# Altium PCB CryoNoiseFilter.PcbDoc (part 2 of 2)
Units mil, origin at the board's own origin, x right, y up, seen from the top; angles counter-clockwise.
Board outline 2990 x 2110 mil, 2 copper layers (Top Layer, Bottom Layer); 246 components, 223 nets, 580 pads, 66 vias.
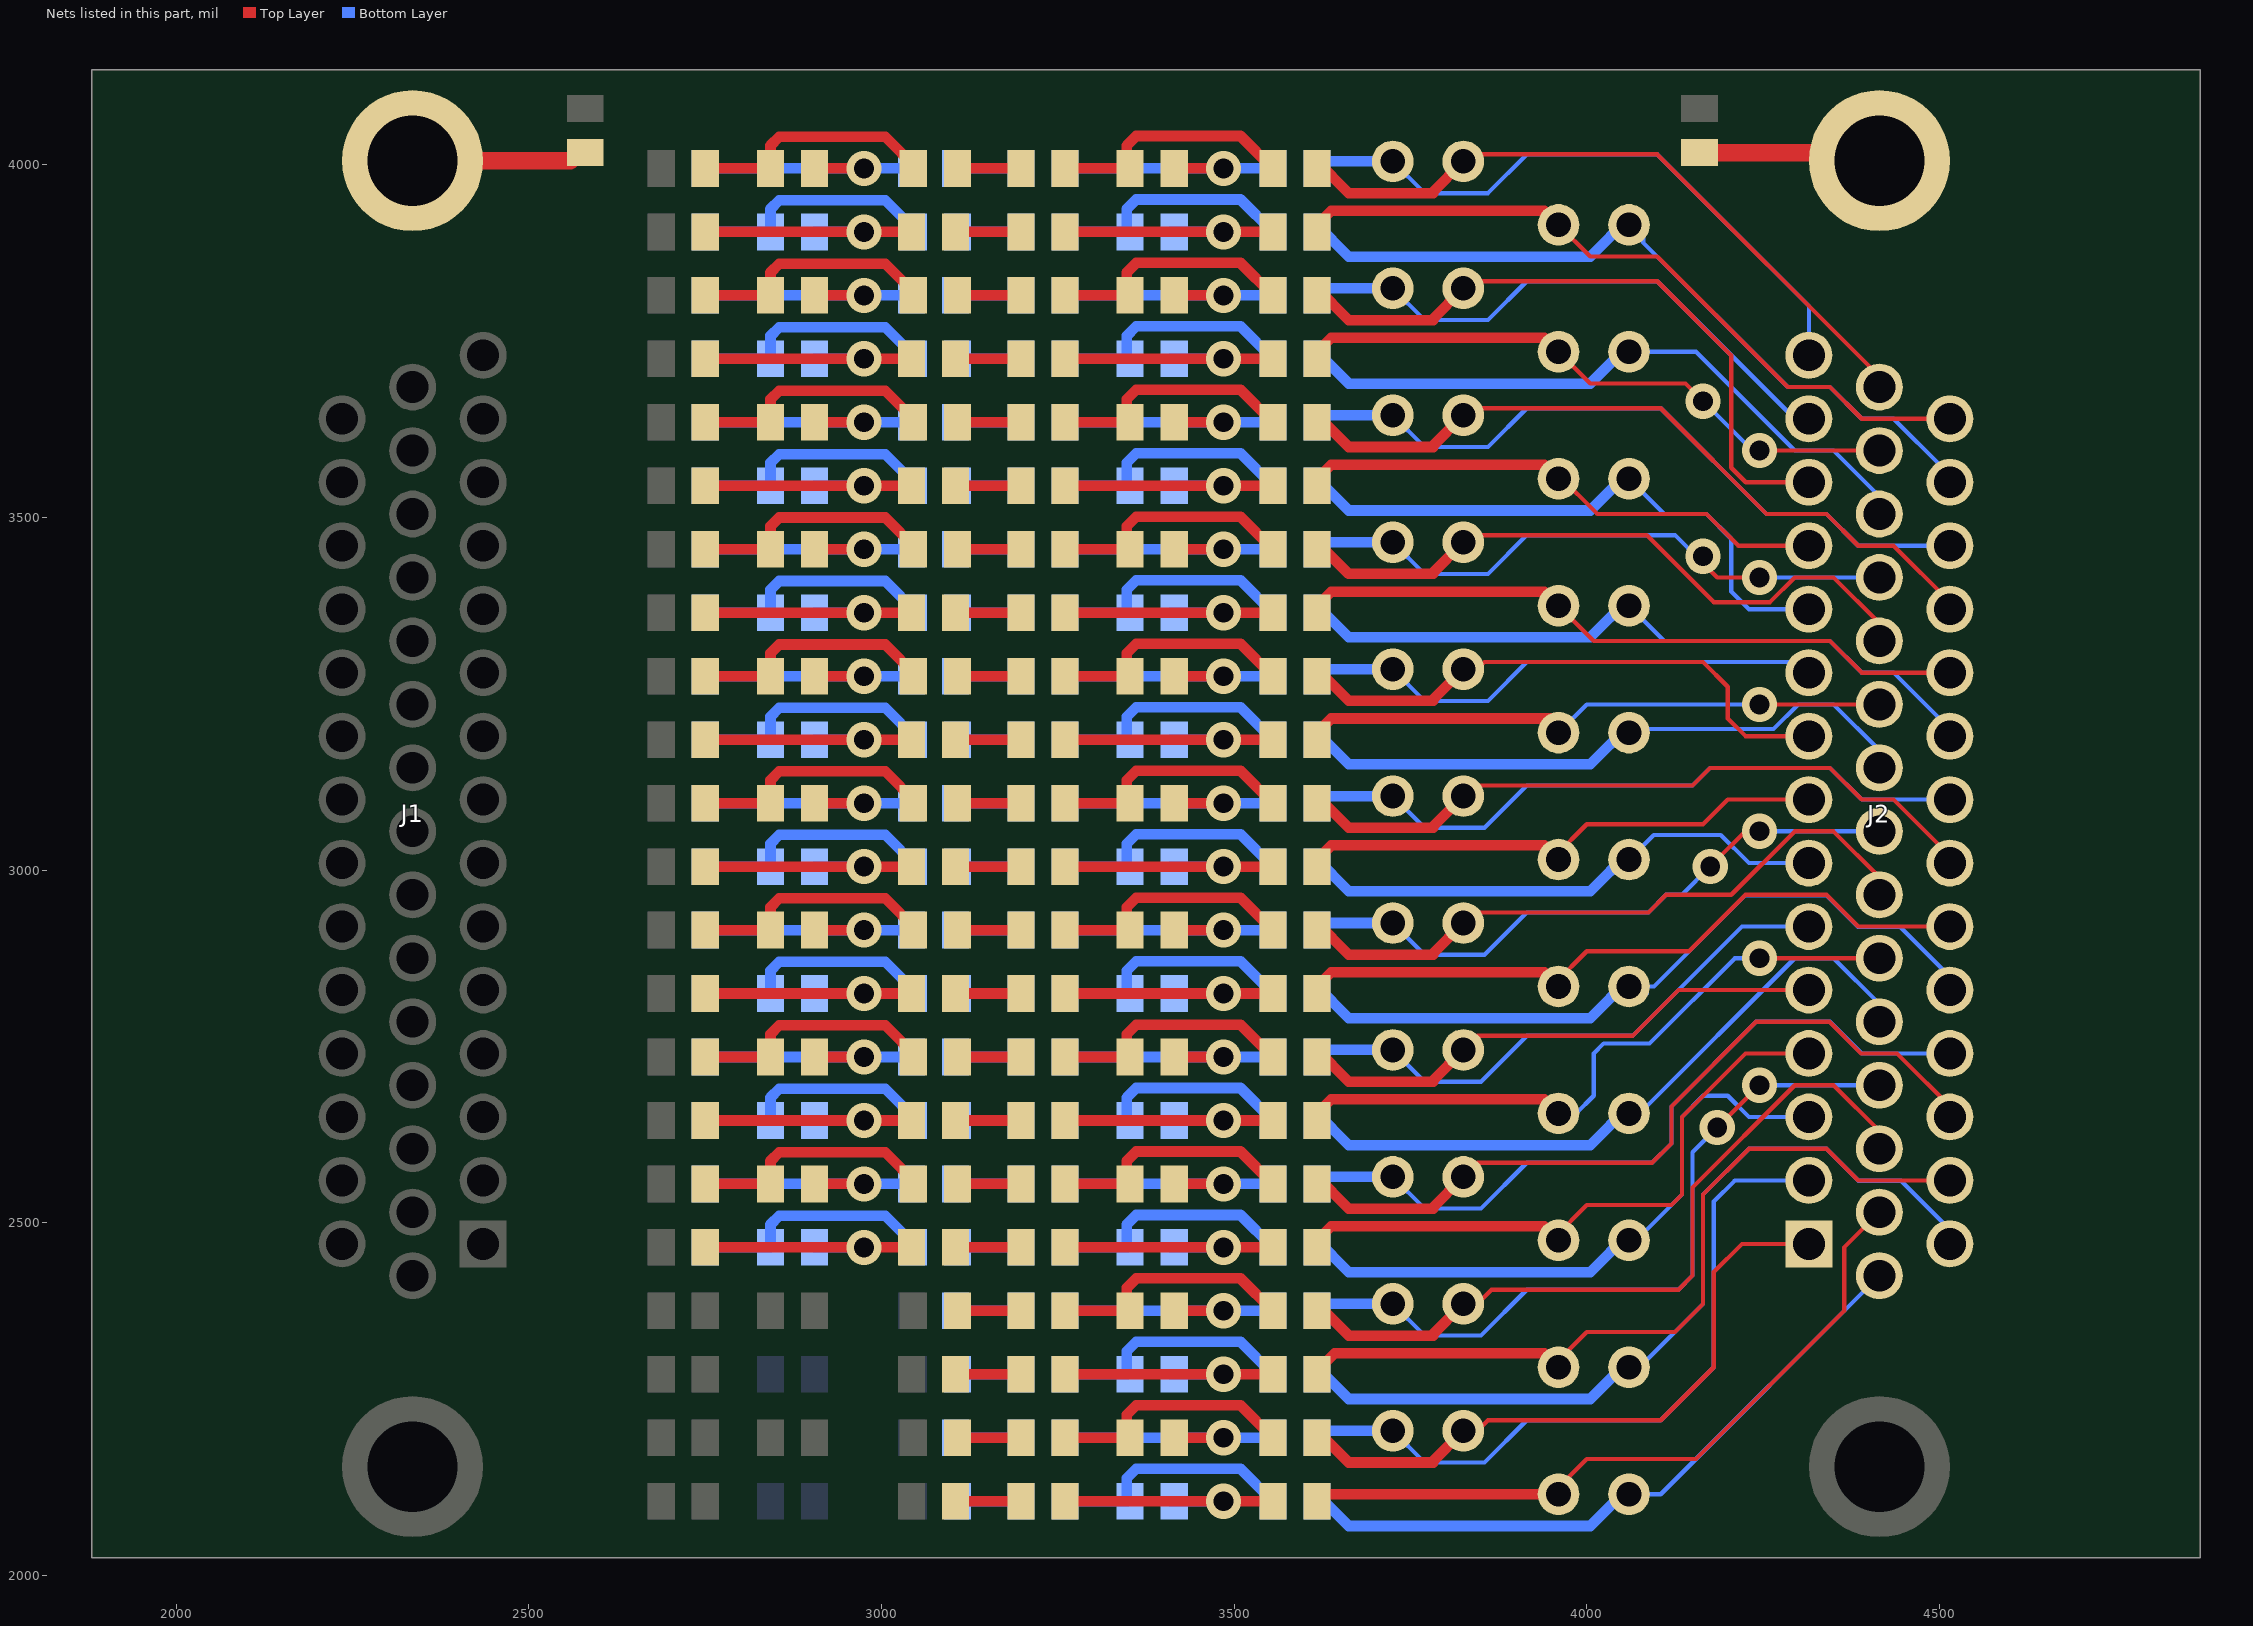
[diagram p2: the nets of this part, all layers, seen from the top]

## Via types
v1: diameter 50, hole 28, Top Layer to Bottom Layer, 66 vias

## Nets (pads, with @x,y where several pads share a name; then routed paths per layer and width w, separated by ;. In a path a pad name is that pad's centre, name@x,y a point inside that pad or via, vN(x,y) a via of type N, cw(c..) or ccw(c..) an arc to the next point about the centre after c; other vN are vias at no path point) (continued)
NetC1_F5_1: C1_F5.1 L4_F5.1 R4_F5.2 | length 367.5
  Top Layer w15: R4_F5.2@2750,2465 v1(2975,2465) L4_F5.1@3042.5,2465 L4_F5.1@3047.5,2465
  Bottom Layer w15: C1_F5.1@2905,2465 v1(2975,2465)
NetC1_F5_2: C1_F5.2 L3_F5.1 R1_F5.2 | length 356.3
  Bottom Layer w15: R1_F5.2@2750,2465 C1_F5.2@2842.5,2465 2842.5,2497.5 2855,2510 3005,2510 L3_F5.1@3050,2465
NetC1_F6_1: C1_F6.1 L4_F6.1 R4_F6.2 | length 367.5
  Top Layer w15: C1_F6.1@2905,2555 v1(2975,2555)
  Bottom Layer w15: R4_F6.2@2750,2555 v1(2975,2555) L4_F6.1@3042.5,2555 L4_F6.1@3047.5,2555
NetC1_F6_2: C1_F6.2 L3_F6.1 R1_F6.2 | length 356.3
  Top Layer w15: R1_F6.2@2750,2555 C1_F6.2@2842.5,2555 2842.5,2587.5 2855,2600 3005,2600 L3_F6.1@3050,2555
NetC1_F7_1: C1_F7.1 L4_F7.1 R4_F7.2 | length 367.5
  Top Layer w15: R4_F7.2@2750,2645 v1(2975,2645) L4_F7.1@3042.5,2645 L4_F7.1@3047.5,2645
  Bottom Layer w15: C1_F7.1@2905,2645 v1(2975,2645)
NetC1_F7_2: C1_F7.2 L3_F7.1 R1_F7.2 | length 356.3
  Bottom Layer w15: R1_F7.2@2750,2645 C1_F7.2@2842.5,2645 2842.5,2677.5 2855,2690 3005,2690 L3_F7.1@3050,2645
NetC1_F8_1: C1_F8.1 L4_F8.1 R4_F8.2 | length 367.5
  Top Layer w15: C1_F8.1@2905,2735 v1(2975,2735)
  Bottom Layer w15: R4_F8.2@2750,2735 v1(2975,2735) L4_F8.1@3042.5,2735 L4_F8.1@3047.5,2735
NetC1_F8_2: C1_F8.2 L3_F8.1 R1_F8.2 | length 356.3
  Top Layer w15: R1_F8.2@2750,2735 C1_F8.2@2842.5,2735 2842.5,2767.5 2855,2780 3005,2780 L3_F8.1@3050,2735
NetC1_F9_1: C1_F9.1 L4_F9.1 R4_F9.2 | length 367.5
  Top Layer w15: R4_F9.2@2750,2825 v1(2975,2825) L4_F9.1@3042.5,2825 L4_F9.1@3047.5,2825
  Bottom Layer w15: C1_F9.1@2905,2825 v1(2975,2825)
NetC1_F9_2: C1_F9.2 L3_F9.1 R1_F9.2 | length 356.3
  Bottom Layer w15: R1_F9.2@2750,2825 C1_F9.2@2842.5,2825 2842.5,2857.5 2855,2870 3005,2870 L3_F9.1@3050,2825
NetC1_F10_1: C1_F10.1 L4_F10.1 R4_F10.2 | length 367.5
  Top Layer w15: C1_F10.1@2905,2915 v1(2975,2915)
  Bottom Layer w15: R4_F10.2@2750,2915 v1(2975,2915) L4_F10.1@3042.5,2915 L4_F10.1@3047.5,2915
NetC1_F10_2: C1_F10.2 L3_F10.1 R1_F10.2 | length 356.3
  Top Layer w15: R1_F10.2@2750,2915 C1_F10.2@2842.5,2915 2842.5,2947.5 2855,2960 3005,2960 L3_F10.1@3050,2915
NetC1_F11_1: C1_F11.1 L4_F11.1 R4_F11.2 | length 367.5
  Top Layer w15: R4_F11.2@2750,3005 v1(2975,3005) L4_F11.1@3042.5,3005 L4_F11.1@3047.5,3005
  Bottom Layer w15: C1_F11.1@2905,3005 v1(2975,3005)
NetC1_F11_2: C1_F11.2 L3_F11.1 R1_F11.2 | length 356.3
  Bottom Layer w15: R1_F11.2@2750,3005 C1_F11.2@2842.5,3005 2842.5,3037.5 2855,3050 3005,3050 L3_F11.1@3050,3005
NetC1_F12_1: C1_F12.1 L4_F12.1 R4_F12.2 | length 367.5
  Top Layer w15: C1_F12.1@2905,3095 v1(2975,3095)
  Bottom Layer w15: R4_F12.2@2750,3095 v1(2975,3095) L4_F12.1@3042.5,3095 L4_F12.1@3047.5,3095
NetC1_F12_2: C1_F12.2 L3_F12.1 R1_F12.2 | length 356.3
  Top Layer w15: R1_F12.2@2750,3095 C1_F12.2@2842.5,3095 2842.5,3127.5 2855,3140 3005,3140 L3_F12.1@3050,3095
NetC1_F13_1: C1_F13.1 L4_F13.1 R4_F13.2 | length 367.5
  Top Layer w15: R4_F13.2@2750,3185 v1(2975,3185) L4_F13.1@3042.5,3185 L4_F13.1@3047.5,3185
  Bottom Layer w15: C1_F13.1@2905,3185 v1(2975,3185)
NetC1_F13_2: C1_F13.2 L3_F13.1 R1_F13.2 | length 356.3
  Bottom Layer w15: R1_F13.2@2750,3185 C1_F13.2@2842.5,3185 2842.5,3217.5 2855,3230 3005,3230 L3_F13.1@3050,3185
NetC1_F14_1: C1_F14.1 L4_F14.1 R4_F14.2 | length 367.5
  Top Layer w15: C1_F14.1@2905,3275 v1(2975,3275)
  Bottom Layer w15: R4_F14.2@2750,3275 v1(2975,3275) L4_F14.1@3042.5,3275 L4_F14.1@3047.5,3275
NetC1_F14_2: C1_F14.2 L3_F14.1 R1_F14.2 | length 356.3
  Top Layer w15: R1_F14.2@2750,3275 C1_F14.2@2842.5,3275 2842.5,3307.5 2855,3320 3005,3320 L3_F14.1@3050,3275
NetC1_F15_1: C1_F15.1 L4_F15.1 R4_F15.2 | length 367.5
  Top Layer w15: R4_F15.2@2750,3365 v1(2975,3365) L4_F15.1@3042.5,3365 L4_F15.1@3047.5,3365
  Bottom Layer w15: C1_F15.1@2905,3365 v1(2975,3365)
NetC1_F15_2: C1_F15.2 L3_F15.1 R1_F15.2 | length 356.3
  Bottom Layer w15: R1_F15.2@2750,3365 C1_F15.2@2842.5,3365 2842.5,3397.5 2855,3410 3005,3410 L3_F15.1@3050,3365
NetC1_F16_1: C1_F16.1 L4_F16.1 R4_F16.2 | length 367.5
  Top Layer w15: C1_F16.1@2905,3455 v1(2975,3455)
  Bottom Layer w15: R4_F16.2@2750,3455 v1(2975,3455) L4_F16.1@3042.5,3455 L4_F16.1@3047.5,3455
NetC1_F16_2: C1_F16.2 L3_F16.1 R1_F16.2 | length 356.3
  Top Layer w15: R1_F16.2@2750,3455 C1_F16.2@2842.5,3455 2842.5,3487.5 2855,3500 3005,3500 L3_F16.1@3050,3455
NetC1_F17_1: C1_F17.1 L4_F17.1 R4_F17.2 | length 367.5
  Top Layer w15: R4_F17.2@2750,3545 v1(2975,3545) L4_F17.1@3042.5,3545 L4_F17.1@3047.5,3545
  Bottom Layer w15: C1_F17.1@2905,3545 v1(2975,3545)
NetC1_F17_2: C1_F17.2 L3_F17.1 R1_F17.2 | length 356.3
  Bottom Layer w15: R1_F17.2@2750,3545 C1_F17.2@2842.5,3545 2842.5,3577.5 2855,3590 3005,3590 L3_F17.1@3050,3545
NetC1_F18_1: C1_F18.1 L4_F18.1 R4_F18.2 | length 367.5
  Top Layer w15: C1_F18.1@2905,3635 v1(2975,3635)
  Bottom Layer w15: R4_F18.2@2750,3635 v1(2975,3635) L4_F18.1@3042.5,3635 L4_F18.1@3047.5,3635
NetC1_F18_2: C1_F18.2 L3_F18.1 R1_F18.2 | length 356.3
  Top Layer w15: R1_F18.2@2750,3635 C1_F18.2@2842.5,3635 2842.5,3667.5 2855,3680 3005,3680 L3_F18.1@3050,3635
NetC1_F19_1: C1_F19.1 L4_F19.1 R4_F19.2 | length 367.5
  Top Layer w15: R4_F19.2@2750,3725 v1(2975,3725) L4_F19.1@3042.5,3725 L4_F19.1@3047.5,3725
  Bottom Layer w15: C1_F19.1@2905,3725 v1(2975,3725)
NetC1_F19_2: C1_F19.2 L3_F19.1 R1_F19.2 | length 356.3
  Bottom Layer w15: R1_F19.2@2750,3725 C1_F19.2@2842.5,3725 2842.5,3757.5 2855,3770 3005,3770 L3_F19.1@3050,3725
NetC1_F20_1: C1_F20.1 L4_F20.1 R4_F20.2 | length 367.5
  Top Layer w15: C1_F20.1@2905,3815 v1(2975,3815)
  Bottom Layer w15: R4_F20.2@2750,3815 v1(2975,3815) L4_F20.1@3042.5,3815 L4_F20.1@3047.5,3815
NetC1_F20_2: C1_F20.2 L3_F20.1 R1_F20.2 | length 356.3
  Top Layer w15: R1_F20.2@2750,3815 C1_F20.2@2842.5,3815 2842.5,3847.5 2855,3860 3005,3860 L3_F20.1@3050,3815
NetC1_F21_1: C1_F21.1 L4_F21.1 R4_F21.2 | length 367.5
  Top Layer w15: R4_F21.2@2750,3905 v1(2975,3905) L4_F21.1@3042.5,3905 L4_F21.1@3047.5,3905
  Bottom Layer w15: C1_F21.1@2905,3905 v1(2975,3905)
NetC1_F21_2: C1_F21.2 L3_F21.1 R1_F21.2 | length 356.3
  Bottom Layer w15: R1_F21.2@2750,3905 C1_F21.2@2842.5,3905 2842.5,3937.5 2855,3950 3005,3950 L3_F21.1@3050,3905
NetC1_F22_1: C1_F22.1 L4_F22.1 R4_F22.2 | length 367.5
  Top Layer w15: C1_F22.1@2905,3995 v1(2975,3995)
  Bottom Layer w15: R4_F22.2@2750,3995 v1(2975,3995) L4_F22.1@3042.5,3995 L4_F22.1@3047.5,3995
NetC1_F22_2: C1_F22.2 L3_F22.1 R1_F22.2 | length 356.3
  Top Layer w15: R1_F22.2@2750,3995 C1_F22.2@2842.5,3995 2842.5,4027.5 2855,4040 3005,4040 L3_F22.1@3050,3995
NetC2_F1_1: C2_F1.1 R5_F1.2 R6_F1.1 | length 365
  Top Layer w15: R5_F1.2@3260,2105 v1(3485,2105) R6_F1.1@3555,2105
  Bottom Layer w15: C2_F1.1@3410,2105 C2_F1.1@3415,2105 v1@3480,2105
NetC2_F1_2: C2_F1.2 R2_F1.2 R3_F1.1 | length 352.1
  Bottom Layer w15: R2_F1.2@3260,2105 3347.5,2105 3347.5,2137.5 3361,2151 3509,2151 R3_F1.1@3555,2105
NetC2_F2_1: C2_F2.1 R5_F2.2 R6_F2.1 | length 365
  Top Layer w15: C2_F2.1@3410,2195 C2_F2.1@3415,2195 v1@3480,2195
  Bottom Layer w15: R5_F2.2@3260,2195 v1(3485,2195) R6_F2.1@3555,2195
NetC2_F2_2: C2_F2.2 R2_F2.2 R3_F2.1 | length 352.1
  Top Layer w15: R2_F2.2@3260,2195 3347.5,2195 3347.5,2227.5 3361,2241 3509,2241 R3_F2.1@3555,2195
NetC2_F3_1: C2_F3.1 R5_F3.2 R6_F3.1 | length 365
  Top Layer w15: R5_F3.2@3260,2285 v1(3485,2285) R6_F3.1@3555,2285
  Bottom Layer w15: C2_F3.1@3410,2285 C2_F3.1@3415,2285 v1@3480,2285
NetC2_F3_2: C2_F3.2 R2_F3.2 R3_F3.1 | length 352.1
  Bottom Layer w15: R2_F3.2@3260,2285 3347.5,2285 3347.5,2317.5 3361,2331 3509,2331 R3_F3.1@3555,2285
NetC2_F4_1: C2_F4.1 R5_F4.2 R6_F4.1 | length 365
  Top Layer w15: C2_F4.1@3410,2375 C2_F4.1@3415,2375 v1@3480,2375
  Bottom Layer w15: R5_F4.2@3260,2375 v1(3485,2375) R6_F4.1@3555,2375
NetC2_F4_2: C2_F4.2 R2_F4.2 R3_F4.1 | length 352.1
  Top Layer w15: R2_F4.2@3260,2375 3347.5,2375 3347.5,2407.5 3361,2421 3509,2421 R3_F4.1@3555,2375
NetC2_F5_1: C2_F5.1 R5_F5.2 R6_F5.1 | length 365
  Top Layer w15: R5_F5.2@3260,2465 v1(3485,2465) R6_F5.1@3555,2465
  Bottom Layer w15: C2_F5.1@3410,2465 C2_F5.1@3415,2465 v1@3480,2465
NetC2_F5_2: C2_F5.2 R2_F5.2 R3_F5.1 | length 352.1
  Bottom Layer w15: R2_F5.2@3260,2465 3347.5,2465 3347.5,2497.5 3361,2511 3509,2511 R3_F5.1@3555,2465
NetC2_F6_1: C2_F6.1 R5_F6.2 R6_F6.1 | length 365
  Top Layer w15: C2_F6.1@3410,2555 C2_F6.1@3415,2555 v1@3480,2555
  Bottom Layer w15: R5_F6.2@3260,2555 v1(3485,2555) R6_F6.1@3555,2555
NetC2_F6_2: C2_F6.2 R2_F6.2 R3_F6.1 | length 352.1
  Top Layer w15: R2_F6.2@3260,2555 3347.5,2555 3347.5,2587.5 3361,2601 3509,2601 R3_F6.1@3555,2555
NetC2_F7_1: C2_F7.1 R5_F7.2 R6_F7.1 | length 365
  Top Layer w15: R5_F7.2@3260,2645 v1(3485,2645) R6_F7.1@3555,2645
  Bottom Layer w15: C2_F7.1@3410,2645 C2_F7.1@3415,2645 v1@3480,2645
NetC2_F7_2: C2_F7.2 R2_F7.2 R3_F7.1 | length 352.1
  Bottom Layer w15: R2_F7.2@3260,2645 3347.5,2645 3347.5,2677.5 3361,2691 3509,2691 R3_F7.1@3555,2645
NetC2_F8_1: C2_F8.1 R5_F8.2 R6_F8.1 | length 365
  Top Layer w15: C2_F8.1@3410,2735 C2_F8.1@3415,2735 v1@3480,2735
  Bottom Layer w15: R5_F8.2@3260,2735 v1(3485,2735) R6_F8.1@3555,2735
NetC2_F8_2: C2_F8.2 R2_F8.2 R3_F8.1 | length 352.1
  Top Layer w15: R2_F8.2@3260,2735 3347.5,2735 3347.5,2767.5 3361,2781 3509,2781 R3_F8.1@3555,2735
NetC2_F9_1: C2_F9.1 R5_F9.2 R6_F9.1 | length 365
  Top Layer w15: R5_F9.2@3260,2825 v1(3485,2825) R6_F9.1@3555,2825
  Bottom Layer w15: C2_F9.1@3410,2825 C2_F9.1@3415,2825 v1@3480,2825
NetC2_F9_2: C2_F9.2 R2_F9.2 R3_F9.1 | length 352.1
  Bottom Layer w15: R2_F9.2@3260,2825 3347.5,2825 3347.5,2857.5 3361,2871 3509,2871 R3_F9.1@3555,2825
NetC2_F10_1: C2_F10.1 R5_F10.2 R6_F10.1 | length 365
  Top Layer w15: C2_F10.1@3410,2915 C2_F10.1@3415,2915 v1@3480,2915
  Bottom Layer w15: R5_F10.2@3260,2915 v1(3485,2915) R6_F10.1@3555,2915
NetC2_F10_2: C2_F10.2 R2_F10.2 R3_F10.1 | length 352.1
  Top Layer w15: R2_F10.2@3260,2915 3347.5,2915 3347.5,2947.5 3361,2961 3509,2961 R3_F10.1@3555,2915
NetC2_F11_1: C2_F11.1 R5_F11.2 R6_F11.1 | length 365
  Top Layer w15: R5_F11.2@3260,3005 v1(3485,3005) R6_F11.1@3555,3005
  Bottom Layer w15: C2_F11.1@3410,3005 C2_F11.1@3415,3005 v1@3480,3005
NetC2_F11_2: C2_F11.2 R2_F11.2 R3_F11.1 | length 352.1
  Bottom Layer w15: R2_F11.2@3260,3005 3347.5,3005 3347.5,3037.5 3361,3051 3509,3051 R3_F11.1@3555,3005
NetC2_F12_1: C2_F12.1 R5_F12.2 R6_F12.1 | length 365
  Top Layer w15: C2_F12.1@3410,3095 C2_F12.1@3415,3095 v1@3480,3095
  Bottom Layer w15: R5_F12.2@3260,3095 v1(3485,3095) R6_F12.1@3555,3095
NetC2_F12_2: C2_F12.2 R2_F12.2 R3_F12.1 | length 352.1
  Top Layer w15: R2_F12.2@3260,3095 3347.5,3095 3347.5,3127.5 3361,3141 3509,3141 R3_F12.1@3555,3095
NetC2_F13_1: C2_F13.1 R5_F13.2 R6_F13.1 | length 365
  Top Layer w15: R5_F13.2@3260,3185 v1(3485,3185) R6_F13.1@3555,3185
  Bottom Layer w15: C2_F13.1@3410,3185 C2_F13.1@3415,3185 v1@3480,3185
NetC2_F13_2: C2_F13.2 R2_F13.2 R3_F13.1 | length 352.1
  Bottom Layer w15: R2_F13.2@3260,3185 3347.5,3185 3347.5,3217.5 3361,3231 3509,3231 R3_F13.1@3555,3185
NetC2_F14_1: C2_F14.1 R5_F14.2 R6_F14.1 | length 365
  Top Layer w15: C2_F14.1@3410,3275 C2_F14.1@3415,3275 v1@3480,3275
  Bottom Layer w15: R5_F14.2@3260,3275 v1(3485,3275) R6_F14.1@3555,3275
NetC2_F14_2: C2_F14.2 R2_F14.2 R3_F14.1 | length 352.1
  Top Layer w15: R2_F14.2@3260,3275 3347.5,3275 3347.5,3307.5 3361,3321 3509,3321 R3_F14.1@3555,3275
NetC2_F15_1: C2_F15.1 R5_F15.2 R6_F15.1 | length 365
  Top Layer w15: R5_F15.2@3260,3365 v1(3485,3365) R6_F15.1@3555,3365
  Bottom Layer w15: C2_F15.1@3410,3365 C2_F15.1@3415,3365 v1@3480,3365
NetC2_F15_2: C2_F15.2 R2_F15.2 R3_F15.1 | length 352.1
  Bottom Layer w15: R2_F15.2@3260,3365 3347.5,3365 3347.5,3397.5 3361,3411 3509,3411 R3_F15.1@3555,3365
NetC2_F16_1: C2_F16.1 R5_F16.2 R6_F16.1 | length 365
  Top Layer w15: C2_F16.1@3410,3455 C2_F16.1@3415,3455 v1@3480,3455
  Bottom Layer w15: R5_F16.2@3260,3455 v1(3485,3455) R6_F16.1@3555,3455
NetC2_F16_2: C2_F16.2 R2_F16.2 R3_F16.1 | length 352.1
  Top Layer w15: R2_F16.2@3260,3455 3347.5,3455 3347.5,3487.5 3361,3501 3509,3501 R3_F16.1@3555,3455
NetC2_F17_1: C2_F17.1 R5_F17.2 R6_F17.1 | length 365
  Top Layer w15: R5_F17.2@3260,3545 v1(3485,3545) R6_F17.1@3555,3545
  Bottom Layer w15: C2_F17.1@3410,3545 C2_F17.1@3415,3545 v1@3480,3545
NetC2_F17_2: C2_F17.2 R2_F17.2 R3_F17.1 | length 352.1
  Bottom Layer w15: R2_F17.2@3260,3545 3347.5,3545 3347.5,3577.5 3361,3591 3509,3591 R3_F17.1@3555,3545
NetC2_F18_1: C2_F18.1 R5_F18.2 R6_F18.1 | length 365
  Top Layer w15: C2_F18.1@3410,3635 C2_F18.1@3415,3635 v1@3480,3635
  Bottom Layer w15: R5_F18.2@3260,3635 v1(3485,3635) R6_F18.1@3555,3635
NetC2_F18_2: C2_F18.2 R2_F18.2 R3_F18.1 | length 352.1
  Top Layer w15: R2_F18.2@3260,3635 3347.5,3635 3347.5,3667.5 3361,3681 3509,3681 R3_F18.1@3555,3635
NetC2_F19_1: C2_F19.1 R5_F19.2 R6_F19.1 | length 365
  Top Layer w15: R5_F19.2@3260,3725 v1(3485,3725) R6_F19.1@3555,3725
  Bottom Layer w15: C2_F19.1@3410,3725 C2_F19.1@3415,3725 v1@3480,3725
NetC2_F19_2: C2_F19.2 R2_F19.2 R3_F19.1 | length 352.1
  Bottom Layer w15: R2_F19.2@3260,3725 3347.5,3725 3347.5,3757.5 3361,3771 3509,3771 R3_F19.1@3555,3725
NetC2_F20_1: C2_F20.1 R5_F20.2 R6_F20.1 | length 365
  Top Layer w15: C2_F20.1@3410,3815 C2_F20.1@3415,3815 v1@3480,3815
  Bottom Layer w15: R5_F20.2@3260,3815 v1(3485,3815) R6_F20.1@3555,3815
NetC2_F20_2: C2_F20.2 R2_F20.2 R3_F20.1 | length 352.1
  Top Layer w15: R2_F20.2@3260,3815 3347.5,3815 3347.5,3847.5 3361,3861 3509,3861 R3_F20.1@3555,3815
NetC2_F21_1: C2_F21.1 R5_F21.2 R6_F21.1 | length 365
  Top Layer w15: R5_F21.2@3260,3905 v1(3485,3905) R6_F21.1@3555,3905
  Bottom Layer w15: C2_F21.1@3410,3905 C2_F21.1@3415,3905 v1@3480,3905
NetC2_F21_2: C2_F21.2 R2_F21.2 R3_F21.1 | length 352.1
  Bottom Layer w15: R2_F21.2@3260,3905 3347.5,3905 3347.5,3937.5 3361,3951 3509,3951 R3_F21.1@3555,3905
NetC2_F22_1: C2_F22.1 R5_F22.2 R6_F22.1 | length 365
  Top Layer w15: C2_F22.1@3410,3995 C2_F22.1@3415,3995 v1@3480,3995
  Bottom Layer w15: R5_F22.2@3260,3995 v1(3485,3995) R6_F22.1@3555,3995
NetC2_F22_2: C2_F22.2 R2_F22.2 R3_F22.1 | length 352.1
  Top Layer w15: R2_F22.2@3260,3995 3347.5,3995 3347.5,4027.5 3361,4041 3509,4041 R3_F22.1@3555,3995
NetJ1_46: J1.46 L1.2 | length 246.8
  Top Layer w25: J1.46@2335,4006 2558.5,4006 L1.2@2575,4022.5
NetJ2_46: J2.46 L2.2 | length 259.8
  Top Layer w25: L2.2@4160,4017.5 4403.5,4017.5 J2.46@4415,4006
NetL3_F1_2: L3_F1.2 R2_F1.1 | length 85
  Bottom Layer w15: L3_F1.2@3112.5,2105 R2_F1.1@3197.5,2105
NetL3_F2_2: L3_F2.2 R2_F2.1 | length 85
  Top Layer w15: L3_F2.2@3112.5,2195 R2_F2.1@3197.5,2195
NetL3_F3_2: L3_F3.2 R2_F3.1 | length 85
  Bottom Layer w15: L3_F3.2@3112.5,2285 R2_F3.1@3197.5,2285
NetL3_F4_2: L3_F4.2 R2_F4.1 | length 85
  Top Layer w15: L3_F4.2@3112.5,2375 R2_F4.1@3197.5,2375
NetL3_F5_2: L3_F5.2 R2_F5.1 | length 85
  Bottom Layer w15: L3_F5.2@3112.5,2465 R2_F5.1@3197.5,2465
NetL3_F6_2: L3_F6.2 R2_F6.1 | length 85
  Top Layer w15: L3_F6.2@3112.5,2555 R2_F6.1@3197.5,2555
NetL3_F7_2: L3_F7.2 R2_F7.1 | length 85
  Bottom Layer w15: L3_F7.2@3112.5,2645 R2_F7.1@3197.5,2645
NetL3_F8_2: L3_F8.2 R2_F8.1 | length 85
  Top Layer w15: L3_F8.2@3112.5,2735 R2_F8.1@3197.5,2735
NetL3_F9_2: L3_F9.2 R2_F9.1 | length 85
  Bottom Layer w15: L3_F9.2@3112.5,2825 R2_F9.1@3197.5,2825
NetL3_F10_2: L3_F10.2 R2_F10.1 | length 85
  Top Layer w15: L3_F10.2@3112.5,2915 R2_F10.1@3197.5,2915
NetL3_F11_2: L3_F11.2 R2_F11.1 | length 85
  Bottom Layer w15: L3_F11.2@3112.5,3005 R2_F11.1@3197.5,3005
NetL3_F12_2: L3_F12.2 R2_F12.1 | length 85
  Top Layer w15: L3_F12.2@3112.5,3095 R2_F12.1@3197.5,3095
NetL3_F13_2: L3_F13.2 R2_F13.1 | length 85
  Bottom Layer w15: L3_F13.2@3112.5,3185 R2_F13.1@3197.5,3185
NetL3_F14_2: L3_F14.2 R2_F14.1 | length 85
  Top Layer w15: L3_F14.2@3112.5,3275 R2_F14.1@3197.5,3275
NetL3_F15_2: L3_F15.2 R2_F15.1 | length 85
  Bottom Layer w15: L3_F15.2@3112.5,3365 R2_F15.1@3197.5,3365
NetL3_F16_2: L3_F16.2 R2_F16.1 | length 85
  Top Layer w15: L3_F16.2@3112.5,3455 R2_F16.1@3197.5,3455
NetL3_F17_2: L3_F17.2 R2_F17.1 | length 85
  Bottom Layer w15: L3_F17.2@3112.5,3545 R2_F17.1@3197.5,3545
NetL3_F18_2: L3_F18.2 R2_F18.1 | length 85
  Top Layer w15: L3_F18.2@3112.5,3635 R2_F18.1@3197.5,3635
NetL3_F19_2: L3_F19.2 R2_F19.1 | length 85
  Bottom Layer w15: L3_F19.2@3112.5,3725 R2_F19.1@3197.5,3725
NetL3_F20_2: L3_F20.2 R2_F20.1 | length 85
  Top Layer w15: L3_F20.2@3112.5,3815 R2_F20.1@3197.5,3815
NetL3_F21_2: L3_F21.2 R2_F21.1 | length 85
  Bottom Layer w15: L3_F21.2@3112.5,3905 R2_F21.1@3197.5,3905
NetL3_F22_2: L3_F22.2 R2_F22.1 | length 85
  Top Layer w15: L3_F22.2@3112.5,3995 R2_F22.1@3197.5,3995
NetL4_F1_2: L4_F1.2 R5_F1.1 | length 87.5
  Top Layer w15: L4_F1.2@3110,2105 R5_F1.1@3197.5,2105
NetL4_F2_2: L4_F2.2 R5_F2.1 | length 87.5
  Bottom Layer w15: L4_F2.2@3110,2195 R5_F2.1@3197.5,2195
NetL4_F3_2: L4_F3.2 R5_F3.1 | length 87.5
  Top Layer w15: L4_F3.2@3110,2285 R5_F3.1@3197.5,2285
NetL4_F4_2: L4_F4.2 R5_F4.1 | length 87.5
  Bottom Layer w15: L4_F4.2@3110,2375 R5_F4.1@3197.5,2375
NetL4_F5_2: L4_F5.2 R5_F5.1 | length 87.5
  Top Layer w15: L4_F5.2@3110,2465 R5_F5.1@3197.5,2465
NetL4_F6_2: L4_F6.2 R5_F6.1 | length 87.5
  Bottom Layer w15: L4_F6.2@3110,2555 R5_F6.1@3197.5,2555
NetL4_F7_2: L4_F7.2 R5_F7.1 | length 87.5
  Top Layer w15: L4_F7.2@3110,2645 R5_F7.1@3197.5,2645
NetL4_F8_2: L4_F8.2 R5_F8.1 | length 87.5
  Bottom Layer w15: L4_F8.2@3110,2735 R5_F8.1@3197.5,2735
NetL4_F9_2: L4_F9.2 R5_F9.1 | length 87.5
  Top Layer w15: L4_F9.2@3110,2825 R5_F9.1@3197.5,2825
NetL4_F10_2: L4_F10.2 R5_F10.1 | length 87.5
  Bottom Layer w15: L4_F10.2@3110,2915 R5_F10.1@3197.5,2915
NetL4_F11_2: L4_F11.2 R5_F11.1 | length 87.5
  Top Layer w15: L4_F11.2@3110,3005 R5_F11.1@3197.5,3005
NetL4_F12_2: L4_F12.2 R5_F12.1 | length 87.5
  Bottom Layer w15: L4_F12.2@3110,3095 R5_F12.1@3197.5,3095
NetL4_F13_2: L4_F13.2 R5_F13.1 | length 87.5
  Top Layer w15: L4_F13.2@3110,3185 R5_F13.1@3197.5,3185
NetL4_F14_2: L4_F14.2 R5_F14.1 | length 87.5
  Bottom Layer w15: L4_F14.2@3110,3275 R5_F14.1@3197.5,3275
NetL4_F15_2: L4_F15.2 R5_F15.1 | length 87.5
  Top Layer w15: L4_F15.2@3110,3365 R5_F15.1@3197.5,3365
NetL4_F16_2: L4_F16.2 R5_F16.1 | length 87.5
  Bottom Layer w15: L4_F16.2@3110,3455 R5_F16.1@3197.5,3455
NetL4_F17_2: L4_F17.2 R5_F17.1 | length 87.5
  Top Layer w15: L4_F17.2@3110,3545 R5_F17.1@3197.5,3545
NetL4_F18_2: L4_F18.2 R5_F18.1 | length 87.5
  Bottom Layer w15: L4_F18.2@3110,3635 R5_F18.1@3197.5,3635
NetL4_F19_2: L4_F19.2 R5_F19.1 | length 87.5
  Top Layer w15: L4_F19.2@3110,3725 R5_F19.1@3197.5,3725
NetL4_F20_2: L4_F20.2 R5_F20.1 | length 87.5
  Bottom Layer w15: L4_F20.2@3110,3815 R5_F20.1@3197.5,3815
NetL4_F21_2: L4_F21.2 R5_F21.1 | length 87.5
  Top Layer w15: L4_F21.2@3110,3905 R5_F21.1@3197.5,3905
NetL4_F22_2: L4_F22.2 R5_F22.1 | length 87.5
  Bottom Layer w15: L4_F22.2@3110,3995 R5_F22.1@3197.5,3995
OUTN1: J2.17 J3_F1.2 R6_F1.2 | length 1035.9
  Top Layer w6: J3_F1.2@3955,2120 4000,2165 4155,2165 4365,2375 4365,2465 J2.17@4415,2515
  Top Layer w15: R6_F1.2@3617.5,2115 3950,2115 J3_F1.2@3955,2120
  Bottom Layer w6: J3_F1.2@3960,2115 J3_F1.2@3980,2115
OUTN2: J2.2 J3_F2.2 R6_F2.2 | length 1019.5
  Bottom Layer w6: J3_F2.2@3725,2205 3770,2160 3855,2160 3915,2220 4105,2220 4180,2295 4180,2530 4210,2560 J2.2@4315,2560
  Bottom Layer w15: R6_F2.2@3617.5,2205 J3_F2.2@3725,2205
OUTN3: J2.32 J3_F3.2 R6_F3.2 | length 1144.8
  Top Layer w6: J3_F3.2@3955,2300 4000,2345 4125,2345 4165,2385 4165,2540 4230,2605 4340,2605 4385,2560 J2.32@4510,2560
  Top Layer w15: R6_F3.2@3617.5,2290 3642.5,2315 3940,2315 J3_F3.2@3955,2300
OUTN4: J2.19 J3_F4.2 R6_F4.2 | length 1065.7
  Top Layer w6: v1(4185,2635) v1(4245,2695)
  Bottom Layer w6: J3_F4.2@3725,2385 3770,2340 3850,2340 3915,2405 4130,2405 4150,2425 4150,2600 v1(4185,2635) ; v1(4245,2695) J2.19@4415,2695
  Bottom Layer w15: R6_F4.2@3617.5,2385 J3_F4.2@3725,2385
OUTN5: J2.4 J3_F5.2 R6_F5.2 | length 884.1
  Top Layer w6: J3_F5.2@3955,2480 4000,2525 4120,2525 4135,2540 4135,2650 4225,2740 J2.4@4315,2740
  Top Layer w15: R6_F5.2@3617.5,2475 3637.5,2495 3940,2495 J3_F5.2@3955,2480
OUTN6: J2.34 J3_F6.2 R6_F6.2 | length 1080.3
  Bottom Layer w6: J3_F6.2@3725,2565 3770,2520 3850,2520 3915,2585 4092.5,2585 4120,2612.5 4120,2665 4240,2785 4345,2785 4390,2740 J2.34@4515,2740 J2.34@4520,2740
  Bottom Layer w15: R6_F6.2@3617.5,2565 J3_F6.2@3725,2565
OUTN7: J2.21 J3_F7.2 R6_F7.2 | length 933.3
  Top Layer w6: v1(4245,2875) J2.21@4415,2875
  Top Layer w15: R6_F7.2@3617.5,2655 3637.5,2675 3940,2675 J3_F7.2@3955,2660
  Bottom Layer w6: J3_F7.2@3960,2655 3985,2655 4010,2680 4010,2740 4024,2754 4089,2754 4210,2875 v1(4245,2875)
OUTN8: J2.6 J3_F8.2 R6_F8.2 | length 807.3
  Bottom Layer w6: J3_F8.2@3725,2745 3770,2700 3850,2700 3915,2765 4065,2765 4220,2920 J2.6@4315,2920
  Bottom Layer w15: R6_F8.2@3617.5,2745 J3_F8.2@3725,2745
OUTN9: J2.36 J3_F9.2 R6_F9.2 | length 977.4
  Top Layer w6: J3_F9.2@3955,2840 4000,2885 4145,2885 4225,2965 4340,2965 4385,2920 J2.36@4510,2920
  Top Layer w15: R6_F9.2@3617.5,2835 3637.5,2855 3940,2855 J3_F9.2@3955,2840
OUTN10: J2.23 J3_F10.2 R6_F10.2 | length 895.7
  Top Layer w6: v1(4175,3005) 4230,3060 4230,3055 v1(4245,3055)
  Bottom Layer w6: J3_F10.2@3725,2925 3770,2880 3855,2880 3915,2940 4087.5,2940 4112.5,2965 4135,2965 v1(4175,3005) ; v1(4245,3055) J2.23@4415,3055
  Bottom Layer w15: R6_F10.2@3617.5,2925 J3_F10.2@3725,2925
OUTN11: J2.8 J3_F11.2 R6_F11.2 | length 745.1
  Top Layer w6: J3_F11.2@3955,3020 4000,3065 4165,3065 4200,3100 J2.8@4315,3100
  Top Layer w15: R6_F11.2@3617.5,3015 3637.5,3035 3940,3035 J3_F11.2@3955,3020
OUTN12: J2.38 J3_F12.2 R6_F12.2 | length 975
  Bottom Layer w6: J3_F12.2@3725,3105 3770,3060 3855,3060 3915,3120 4150,3120 4175,3145 4345,3145 4390,3100 J2.38@4515,3100 J2.38@4520,3100
  Bottom Layer w15: R6_F12.2@3617.5,3105 J3_F12.2@3725,3105
OUTN13: J2.25 J3_F13.2 R6_F13.2 | length 826.5
  Top Layer w6: v1(4245,3235) J2.25@4415,3235
  Top Layer w15: R6_F13.2@3617.5,3195 3637.5,3215 3950,3215 J3_F13.2@3960,3205
  Bottom Layer w6: J3_F13.2@3960,3195 4000,3235 v1(4245,3235)
OUTN14: J2.10 J3_F14.2 R6_F14.2 | length 747.2
  Bottom Layer w6: J3_F14.2@3725,3285 3770,3240 3860,3240 3915,3295 4295,3295 J2.10@4315,3275
  Bottom Layer w15: R6_F14.2@3617.5,3285 J3_F14.2@3725,3285
OUTN15: J2.40 J3_F15.2 R6_F15.2 | length 960.5
  Top Layer w6: J3_F15.2@3955,3380 J3_F15.2@3960,3375 4010,3325 4345,3325 4390,3280 J2.40@4515,3280
  Top Layer w15: R6_F15.2@3617.5,3375 3637.5,3395 3940,3395 3955,3380 J3_F15.2@3960,3385
OUTN16: J2.27 J3_F16.2 R6_F16.2 | length 883.8
  Top Layer w6: v1(4165,3445) 4170,3440 4170,3430 4185,3415 v1(4245,3415)
  Bottom Layer w6: J3_F16.2@3725,3465 3770,3420 3860,3420 3915,3475 4125,3475 4160,3440 4170,3440 v1(4165,3445) ; v1(4245,3415) J2.27@4415,3415
  Bottom Layer w15: R6_F16.2@3617.5,3465 J3_F16.2@3725,3465
OUTN17: J2.12 J3_F17.2 R6_F17.2 | length 760.5
  Top Layer w6: J3_F17.2@3955,3560 3960,3560 4015,3505 4170,3505 4215,3460 J2.12@4315,3460
  Top Layer w15: R6_F17.2@3617.5,3555 3637.5,3575 3940,3575 3955,3560 J3_F17.2@3960,3565
OUTN18: J2.42 J3_F18.2 R6_F18.2 | length 1019.7
  Bottom Layer w6: J3_F18.2@3725,3645 3770,3600 3860,3600 3915,3655 4105,3655 4255,3505 4340,3505 4385,3460 J2.42@4515,3460
  Bottom Layer w15: R6_F18.2@3617.5,3645 J3_F18.2@3725,3645
OUTN19: J2.29 J3_F19.2 R6_F19.2 | length 908.3
  Top Layer w6: J3_F19.2@3955,3740 J3_F19.2@3960,3735 4005,3690 4140,3690 v1(4165,3665) ; v1(4245,3595) J2.29@4415,3595
  Top Layer w15: R6_F19.2@3617.5,3735 3637.5,3755 3940,3755 3955,3740 J3_F19.2@3960,3745
  Bottom Layer w6: v1@4165,3650 4160,3655 4160,3670 v1(4165,3665) 4235,3595 v1(4245,3595)
OUTN20: J2.14 J3_F20.2 R6_F20.2 | length 819.7
  Bottom Layer w6: J3_F20.2@3725,3825 3770,3780 3860,3780 3915,3835 4100,3835 4295,3640 J2.14@4315,3640
  Bottom Layer w15: R6_F20.2@3617.5,3825 J3_F20.2@3725,3825
OUTN21: J2.44 J3_F21.2 R6_F21.2 | length 1035
  Top Layer w6: J3_F21.2@3955,3920 J3_F21.2@3960,3915 4005,3870 4100,3870 4285,3685 4345,3685 4390,3640 J2.44@4515,3640
  Top Layer w15: R6_F21.2@3617.5,3915 3637.5,3935 3940,3935 3955,3920 J3_F21.2@3960,3925
OUTN22: J2.15 J3_F22.2 R6_F22.2 | length 898
  Bottom Layer w6: J3_F22.2@3725,4005 3770,3960 3860,3960 3915,4015 4100,4015 4315,3800 J2.15@4315,3730
  Bottom Layer w15: R6_F22.2@3617.5,4005 J3_F22.2@3725,4005
OUTP1: J2.16 J3_F1.1 R3_F1.2 | length 982.3
  Bottom Layer w6: J3_F1.1@4060,2115 4105,2115 J2.16@4415,2425 J2.16@4415,2440
  Bottom Layer w15: R3_F1.2@3617.5,2115 3662.5,2070 4005,2070 J3_F1.1@4060,2125
OUTP2: J2.1 J3_F2.1 R3_F2.2 | length 917.8
  Top Layer w6: J3_F2.1@3835,2195 3860,2220 4105,2220 4180,2295 4180,2430 4220,2470 J2.1@4315,2470
  Top Layer w15: R3_F2.2@3617.5,2205 3662.5,2160 ; 3665,2160 3780,2160 ; 3782.5,2160 3780,2160 ; J3_F2.1@3825,2205 3780,2160
OUTP3: J2.31 J3_F3.1 R3_F3.2 | length 1224.4
  Bottom Layer w6: J3_F3.1@4060,2295 4075,2295 4165,2385 4165,2540 4230,2605 4340,2605 4385.5,2559.5 4445.5,2559.5 4510.5,2494.5 J2.31@4510.5,2469.5
  Bottom Layer w15: R3_F3.2@3617.5,2295 3662.5,2250 4005,2250 J3_F3.1@4060,2305
OUTP4: J2.18 J3_F4.1 R3_F4.2 | length 1082.5
  Top Layer w6: J3_F4.1@3835,2375 3865,2405 4130,2405 4150,2425 4150,2550 4295,2695 4350,2695 4415,2630 J2.18@4415,2605
  Top Layer w15: R3_F4.2@3617.5,2385 3662.5,2340 ; 3665,2340 3780,2340 ; 3782.5,2340 3780,2340 ; J3_F4.1@3825,2385 3780,2340
OUTP5: J2.3 J3_F5.1 R3_F5.2 | length 900.7
  Bottom Layer w6: J3_F5.1@4060,2475 4070,2475 4135,2540 4135,2650 4165,2680 4200,2680 4230,2650 J2.3@4315,2650
  Bottom Layer w15: R3_F5.2@3617.5,2475 3662.5,2430 4005,2430 J3_F5.1@4060,2485
OUTP6: J2.33 J3_F6.1 R3_F6.2 | length 1117
  Top Layer w6: J3_F6.1@3825,2565 3845,2585 4092.5,2585 4120,2612.5 4120,2665 4240,2785 4344,2785 4389,2740 4440,2740 J2.33@4522.5,2657.5
  Top Layer w15: R3_F6.2@3617.5,2565 3662.5,2520 ; 3665,2520 3780,2520 ; 3782.5,2520 3780,2520 ; J3_F6.1@3825,2565 3780,2520
OUTP7: J2.20 J3_F7.1 R3_F7.2 | length 1006.8
  Bottom Layer w6: J3_F7.1@4060,2655 4075,2655 4295,2875 4350,2875 4415,2810 J2.20@4415,2785 ; J3_F7.1@4062.5,2645 4071.25,2653.75 J3_F7.1@4083.75,2653.75
  Bottom Layer w15: R3_F7.2@3617.5,2655 3662.5,2610 4005,2610 J3_F7.1@4060,2665
OUTP8: J2.5 J3_F8.1 R3_F8.2 | length 770
  Top Layer w6: J3_F8.1@3825,2745 3845,2765 4065,2765 4130,2830 J2.5@4315,2830
  Top Layer w15: R3_F8.2@3617.5,2745 3662.5,2700 ; 3665,2700 3780,2700 ; 3782.5,2700 3780,2700 ; J3_F8.1@3825,2745 3780,2700
OUTP9: J2.35 J3_F9.1 R3_F9.2 | length 1080.6
  Bottom Layer w6: J3_F9.1@4060,2835 4095.5,2835 4225,2964.5 4339.5,2964.5 4384.5,2919.5 4444.5,2919.5 4509.5,2854.5 J2.35@4509.5,2829.5 ; J3_F9.1@4062.5,2825 J3_F9.1@4085.5,2825
  Bottom Layer w15: R3_F9.2@3617.5,2835 3662.5,2790 4005,2790 J3_F9.1@4060,2845
OUTP10: J2.22 J3_F10.1 R3_F10.2 | length 940.6
  Top Layer w6: J3_F10.1@3825,2925 3840,2940 4087.5,2940 4112.5,2965 4205,2965 4295,3055 4350,3055 4415,2990 J2.22@4415,2965
  Top Layer w15: R3_F10.2@3617.5,2925 3662.5,2880 ; 3665,2880 3780,2880 ; 3782.5,2880 3780,2880 ; J3_F10.1@3825,2925 3780,2880
OUTP11: J2.7 J3_F11.1 R3_F11.2 | length 770
  Bottom Layer w6: J3_F11.1@4060,3015 4095,3050 4190,3050 4230,3010 J2.7@4315,3010
  Bottom Layer w15: R3_F11.2@3617.5,3015 3662.5,2970 4005,2970 J3_F11.1@4060,3025
OUTP12: J2.37 J3_F12.1 R3_F12.2 | length 1013.1
  Top Layer w6: J3_F12.1@3825,3105 3840,3120 4150,3120 4175,3145 4345,3145 4390,3100 4435,3100 4515,3020 J2.37@4515,3010
  Top Layer w15: R3_F12.2@3617.5,3105 3662.5,3060 ; 3665,3060 3780,3060 ; 3782.5,3060 3780,3060 ; J3_F12.1@3825,3105 3780,3060
OUTP13: J2.24 J3_F13.1 R3_F13.2 | length 907.4
  Bottom Layer w6: J3_F13.1@4060,3195 4065,3200 4120,3200 4265,3200 4300,3235 4350,3235 4415,3170 J2.24@4415,3145
  Bottom Layer w15: R3_F13.2@3617.5,3195 3662.5,3150 4005,3150 J3_F13.1@4060,3205
OUTP14: J2.9 J3_F14.1 R3_F14.2 | length 802.9
  Top Layer w6: J3_F14.1@3835,3275 3855,3295 4165,3295 4200,3260 4200,3215 4225,3190 J2.9@4315,3190
  Top Layer w15: R3_F14.2@3617.5,3285 3662.5,3240 ; 3665,3240 3780,3240 ; 3782.5,3240 3780,3240 ; J3_F14.1@3825,3285 3780,3240
OUTP15: J2.39 J3_F15.1 R3_F15.2 | length 1021.4
  Bottom Layer w6: J3_F15.1@4060,3375 4110,3325 4345,3325 4390,3280 4435,3280 4515,3200 J2.39@4515,3190
  Bottom Layer w15: R3_F15.2@3617.5,3375 3662.5,3330 4005,3330 J3_F15.1@4060,3385
OUTP16: J2.26 J3_F16.1 R3_F16.2 | length 944.7
  Top Layer w6: J3_F16.1@3825,3465 3835,3475 4085,3475 4180,3380 4260,3380 4295,3415 4350,3415 4415,3350 J2.26@4415,3325
  Top Layer w15: R3_F16.2@3617.5,3465 3662.5,3420 ; 3665,3420 3780,3420 ; 3782.5,3420 3780,3420 ; J3_F16.1@3825,3465 3780,3420
OUTP17: J2.11 J3_F17.1 R3_F17.2 | length 859.5
  Bottom Layer w6: J3_F17.1@4060,3555 4110,3505 4170,3505 4205,3470 4205,3395 4230,3370 J2.11@4315,3370
  Bottom Layer w15: R3_F17.2@3617.5,3555 3662.5,3510 4005,3510 J3_F17.1@4060,3565
OUTP18: J2.41 J3_F18.1 R3_F18.2 | length 1062.8
  Top Layer w6: J3_F18.1@3825,3645 3835,3655 4105,3655 4255,3505 4340,3505 4385,3460 4435,3460 4515,3380 J2.41@4515,3370
  Top Layer w15: R3_F18.2@3617.5,3645 3662.5,3600 ; 3665,3600 3780,3600 ; 3782.5,3600 3780,3600 ; J3_F18.1@3825,3645 3780,3600
OUTP19: J2.28 J3_F19.1 R3_F19.2 | length 948.8
  Bottom Layer w6: J3_F19.1@4060,3735 4155,3735 4295,3595 4350,3595 4415,3530 J2.28@4415,3505
  Bottom Layer w15: R3_F19.2@3617.5,3735 3662.5,3690 4005,3690 J3_F19.1@4060,3745
OUTP20: J2.13 J3_F20.1 R3_F20.2 | length 950.4
  Top Layer w6: J3_F20.1@3825,3825 3835,3835 4100,3835 4205,3730 4205,3570.56 4225.56,3550 J2.13@4315,3550
  Top Layer w15: R3_F20.2@3617.5,3825 3662.5,3780 ; 3665,3780 3780,3780 ; 3782.5,3780 3780,3780 ; J3_F20.1@3825,3825 3780,3780
OUTP21: J2.43 J3_F21.1 R3_F21.2 | length 1101.5
  Bottom Layer w6: J3_F21.1@4060,3915 4080,3915 4080,3890 4285,3685 4345,3685 4390,3640 4435,3640 4505,3570 J2.43@4520,3570
  Bottom Layer w15: R3_F21.2@3617.5,3915 3662.5,3870 4005,3870 J3_F21.1@4060,3925
OUTP22: J2.30 J3_F22.1 R3_F22.2 | length 984.4
  Top Layer w6: J3_F22.1@3825,4005 3835,4015 4100,4015 4415,3700 J2.30@4415,3685
  Top Layer w15: R3_F22.2@3617.5,4005 3662.5,3960 ; 3665,3960 3780,3960 ; 3782.5,3960 3780,3960 ; J3_F22.1@3825,4005 3780,3960
pads on no net: J1.45 J2.45

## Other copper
Top Layer:
  text "P15" at 3690,4070 h25
  text "P30" at 3795,4070 h25
  text "P44" at 3930,3975 h25
  text "P43" at 4025,3975 h25
  text "P14" at 3690,3890 h25
  text "P13" at 3795,3890 h25
  text "P29" at 3930,3795 h25
  text "P28" at 4025,3795 h25
  text "P42" at 3690,3710 h25
  text "P41" at 3795,3710 h25
  text "P12" at 3935,3615 h25
  text "P11" at 4035,3615 h25
  text "P27" at 3690,3530 h25
  text "P26" at 3800,3530 h25
  text "P40" at 3920,3435 h25
  text "P39" at 4010,3435 h25
  text "P10" at 3690,3350 h25
  text "P9" at 3800,3350 h25
  text "P25" at 3930,3255 h25
  text "P24" at 4035,3255 h25
  text "P38" at 3690,3170 h25
  text "P37" at 3800,3170 h25
  text "P8" at 3930,3080 h25
  text "P7" at 4050,3080 h25
  text "P23" at 3690,2990 h25
  text "P22" at 3805,2990 h25
  text "P36" at 3930,2900 h25
  text "P35" at 4035,2900 h25
  text "P6" at 3700,2810 h25
  text "P5" at 3805,2810 h25
  text "P21" at 3930,2715 h25
  text "P20" at 4035,2715 h25
  text "P34" at 3695,2630 h25
  text "P33" at 3800,2630 h25
  text "P4" at 3935,2540 h25
  text "P3" at 4045,2540 h25
  text "P19" at 3695,2450 h25
  text "P18" at 3800,2450 h25
  text "P32" at 3935,2360 h25
  text "P31" at 4040,2360 h25
  text "P2" at 3695,2270 h25
  text "P1" at 3800,2270 h25
  text "P17" at 3940,2180 h25
  text "P16" at 4040,2180 h25
Bottom Layer:
  text "McGill 2011 - Cryoboard noise filter" at 3630,4095 h30
  text "P15" at 3755,4070 h25
  text "P30" at 3860,4070 h25
  text "adamjohngilbert@gmail.com" at 3625,4050 h30
  text "P44" at 3995,3975 h25
  text "P43" at 4090,3975 h25
  text "P14" at 3755,3890 h25
  text "P13" at 3860,3890 h25
  text "P29" at 3995,3795 h25
  text "P28" at 4090,3795 h25
  text "P42" at 3755,3710 h25
  text "P41" at 3860,3710 h25
  text "P12" at 4000,3615 h25
  text "P11" at 4100,3615 h25
  text "P27" at 3755,3530 h25
  text "P26" at 3865,3530 h25
  text "P40" at 3995,3435 h25
  text "P39" at 4095,3435 h25
  text "P10" at 3755,3350 h25
  text "P9" at 3865,3350 h25
  text "P25" at 3995,3255 h25
  text "P24" at 4100,3255 h25
  text "P38" at 3755,3170 h25
  text "P37" at 3865,3170 h25
  text "P8" at 3995,3080 h25
  text "P7" at 4115,3080 h25
  text "P23" at 3755,2990 h25
  text "P22" at 3870,2990 h25
  text "P36" at 3995,2900 h25
  text "P35" at 4100,2900 h25
  text "P6" at 3765,2810 h25
  text "P5" at 3870,2810 h25
  text "P21" at 3995,2715 h25
  text "P20" at 4100,2715 h25
  text "P34" at 3760,2630 h25
  text "P33" at 3865,2630 h25
  text "P4" at 4000,2540 h25
  text "P3" at 4110,2540 h25
  text "P19" at 3760,2450 h25
  text "P18" at 3865,2450 h25
  text "P32" at 4000,2360 h25
  text "P31" at 4105,2360 h25
  text "P2" at 3760,2270 h25
  text "P1" at 3860,2270 h25
  text "P17" at 4005,2180 h25
  text "P16" at 4105,2180 h25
